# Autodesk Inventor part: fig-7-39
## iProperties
Shininess: 77.0
Length Units: 11269
Angle Units: 11279
Time Units: 11290
Mass Units: 11283
Length Display Precision: 3
Angle Display Precision: 2
Created: 2002-01
Part Number: fig-7-39
Document SubType Name: Modeling
Designer: ***
Density: 1 g/cm^3
Density: 0.0
Volumn: 0.0
Area: 0.0
PropertySet Name: Model Information
Control State: 0
Master: False
Checked Out: False
Author: ***
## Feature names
1. Extrusion1
2. Fillet1
3. Extrusion2
4. Extrusion3
5. Chamfer1
